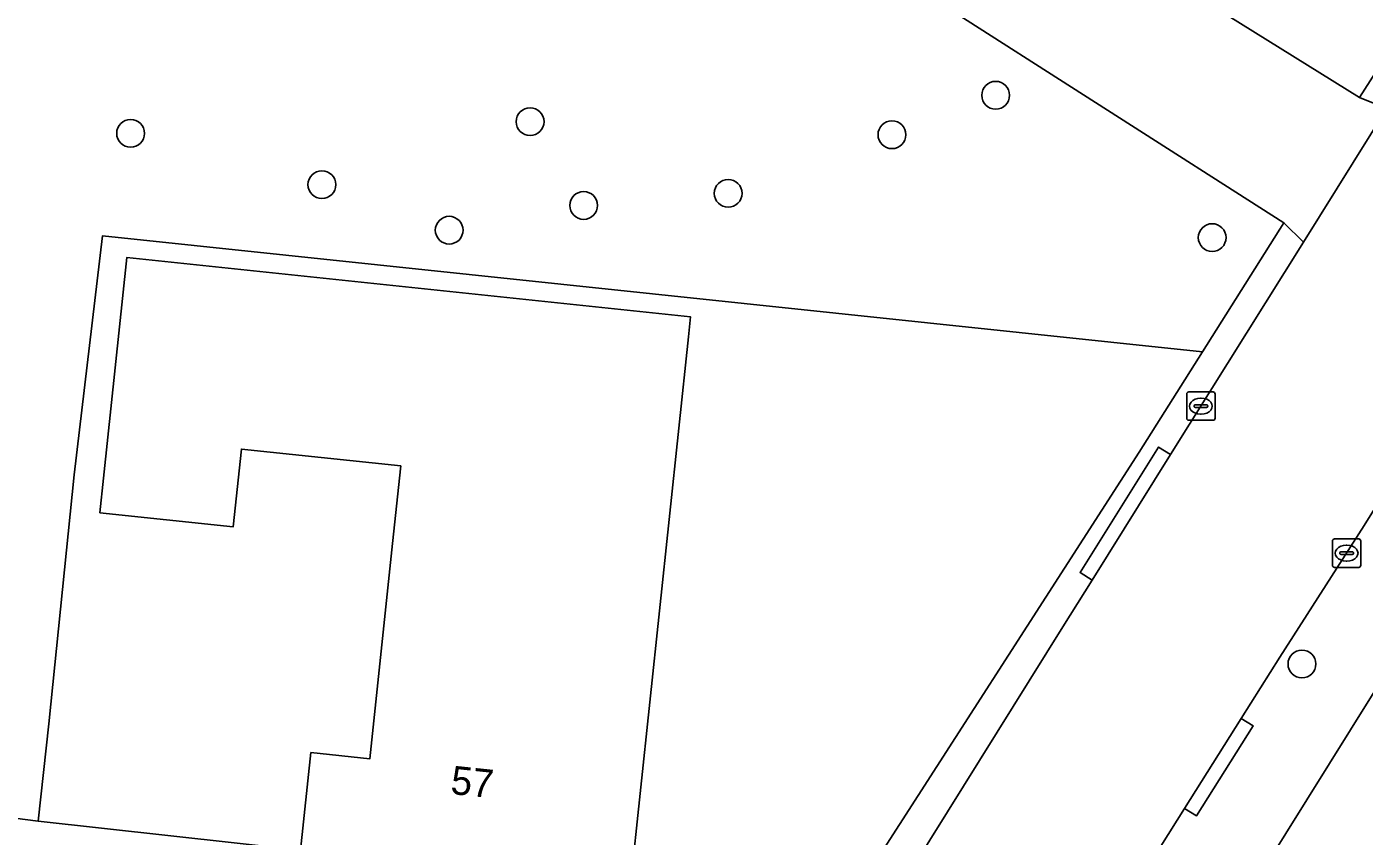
# Model space of a CAD drawing. Extents: x 162396 to 163643, y 386452 to 387406.
# Drawn here: x 162900.94 to 162948.05, y 387017.88 to 387046.39 of the extents above; entities that cross this region are included whole.
import ezdxf

# ---------------------------------------------------------------- set-up
doc = ezdxf.new("R2010")
doc.units = 0
for name, color, linetype in [('IMGEO_Boom', 7, 'Continuous'), ('IMGEO_Erf', 7, 'Continuous'), ('IMGEO_Groenvoorziening', 7, 'Continuous'), ('IMGEO_Kolk', 7, 'Continuous'), ('IMGEO_Pand', 7, 'Continuous'), ('IMGEO_Pand_nummerreeks', 7, 'Continuous'), ('IMGEO_Rijbaan_lokaal_open', 7, 'Continuous'), ('IMGEO_Voetpad_open', 7, 'Continuous')]:
    doc.layers.add(name, color=color, linetype=linetype)

msp = doc.modelspace()

# ---------------------------------------------------------------- linework, layer by layer
at = {"layer": 'IMGEO_Boom'}
for centre in [(162935.067, 387043.977), (162904.598, 387042.636), (162918.67, 387043.047), (162931.413, 387042.586), (162911.336, 387040.83), (162925.645, 387040.521), (162920.557, 387040.096), (162915.82, 387039.225), (162942.692, 387038.965), (162945.853, 387023.948)]:
    msp.add_circle(centre, 0.489, dxfattribs=at)
at = {"layer": 'IMGEO_Erf'}
msp.add_lwpolyline([(162940.119, 387031.406), (162942.349, 387034.94), (162903.611, 387039.027), (162902.613, 387030.613), (162901.724, 387021.841), (162901.346, 387018.415), (162910.588, 387017.396), (162910.951, 387020.828), (162913.025, 387020.609), (162913.826, 387028.186), (162914.115, 387030.921), (162908.504, 387031.514), (162908.215, 387028.779), (162903.517, 387029.275), (162903.646, 387030.495), (162904.467, 387038.268), (162924.323, 387036.171), (162924.249, 387035.467), (162922.211, 387016.169), (162929.704, 387015.236)], close=True, dxfattribs=at)
msp.add_lwpolyline([(162989.314, 387008.671), (162953.541, 387031.202), (162934.073, 387000), (162925.999, 386987.383), (162920.22, 386977.995), (162917.756, 386973.029), (162916.265, 386969.23), (162904.686, 386937.076)], dxfattribs=at)
at = {"layer": 'IMGEO_Groenvoorziening'}
msp.add_lwpolyline([(162964.245, 387069.484), (162941.168, 387071.891), (162939.105, 387055.217), (162936.596, 387055.509), (162935.833, 387055.438), (162935.116, 387055.166), (162934.413, 387053.638), (162934.581, 387052.537), (162935.398, 387051.666), (162947.885, 387043.899)], close=True, dxfattribs=at)
msp.add_lwpolyline([(162884.304, 387046.585), (162885.26, 387045.98), (162886.148, 387045.279), (162888.823, 387042.622), (162893.785, 387046.071), (162900.294, 387045.345), (162898.918, 387024.528), (162893.576, 387025.17), (162892.921, 387019.487), (162901.346, 387018.415), (162901.724, 387021.841), (162902.613, 387030.613), (162903.611, 387039.027), (162942.349, 387034.94), (162945.216, 387039.485), (162932.8, 387047.432)], dxfattribs=at)
at = {"layer": 'IMGEO_Kolk'}
for p, q in [((162941.794, 387032.603), (162941.794, 387033.455)), ((162941.869, 387033.529), (162942.721, 387033.529)), ((162942.282, 387033.309), (162942.307, 387033.309)), ((162942.795, 387033.455), (162942.795, 387032.603)), ((162942.053, 387033.023), (162942.053, 387033.035)), ((162942.491, 387032.986), (162942.093, 387032.986)), ((162942.096, 387033.072), (162942.494, 387033.072)), ((162942.305, 387032.749), (162942.28, 387032.749)), ((162942.537, 387033.035), (162942.537, 387033.023)), ((162942.721, 387032.529), (162941.869, 387032.529)), ((162946.926, 387027.425), (162946.926, 387028.277)), ((162947.001, 387028.351), (162947.853, 387028.351)), ((162947.414, 387028.131), (162947.439, 387028.131)), ((162947.927, 387028.277), (162947.927, 387027.425)), ((162947.185, 387027.845), (162947.185, 387027.857)), ((162947.623, 387027.808), (162947.225, 387027.808)), ((162947.228, 387027.894), (162947.626, 387027.894)), ((162947.437, 387027.571), (162947.412, 387027.571)), ((162947.669, 387027.857), (162947.669, 387027.845)), ((162947.853, 387027.351), (162947.001, 387027.351))]:
    msp.add_line(p, q, dxfattribs=at)
for points in [[(162941.794, 387032.603), (162941.794, 387033.455)], [(162941.869, 387033.529), (162942.721, 387033.529)], [(162942.795, 387033.455), (162942.795, 387032.603)], [(162942.721, 387032.529), (162941.869, 387032.529)], [(162946.926, 387027.425), (162946.926, 387028.277)], [(162947.001, 387028.351), (162947.853, 387028.351)], [(162947.927, 387028.277), (162947.927, 387027.425)], [(162947.853, 387027.351), (162947.001, 387027.351)]]:
    msp.add_lwpolyline(points, dxfattribs=at)
for centre, radius, start, end in [((162941.871, 387033.453), 0.0765, 91.552, 178.448), ((162941.871, 387033.453), 0.0765, 91.552, 178.448), ((162942.719, 387033.453), 0.0765, 1.552, 88.448), ((162942.719, 387033.453), 0.0765, 1.552, 88.448), ((162942.093, 387033.032), 0.0403, 85.8775, 175.7526), ((162942.09, 387033.022), 0.0366, 178.938, 274.7102), ((162942.494, 387033.029), 0.043, 264.8664, 352.4533), ((162942.498, 387033.034), 0.0386, 1.7309, 96.639), ((162941.871, 387032.605), 0.0765, 181.552, 268.448), ((162941.871, 387032.605), 0.0765, 181.552, 268.448), ((162942.719, 387032.605), 0.0765, 271.552, 358.448), ((162942.719, 387032.605), 0.0765, 271.552, 358.448), ((162947.003, 387028.275), 0.0765, 91.552, 178.448), ((162947.003, 387028.275), 0.0765, 91.552, 178.448), ((162947.851, 387028.275), 0.0765, 1.552, 88.448), ((162947.851, 387028.275), 0.0765, 1.552, 88.448), ((162947.225, 387027.854), 0.0403, 85.8775, 175.7526), ((162947.222, 387027.844), 0.0366, 178.938, 274.7102), ((162947.626, 387027.851), 0.043, 264.8664, 352.4533), ((162947.63, 387027.856), 0.0386, 1.7309, 96.639), ((162947.003, 387027.427), 0.0765, 181.552, 268.448), ((162947.003, 387027.427), 0.0765, 181.552, 268.448), ((162947.851, 387027.427), 0.0765, 271.552, 358.448), ((162947.851, 387027.427), 0.0765, 271.552, 358.448)]:
    msp.add_arc(centre, radius, start, end, dxfattribs=at)
for centre, major_axis, ratio, start_param, end_param in [((162942.281, 387033.029), (-0.387, 0.002), 0.722429, 4.712389, 7.853982), ((162942.306, 387033.029), (-0.39, 0.002), 0.717154, 1.570796, 4.712389), ((162947.413, 387027.851), (-0.387, 0.002), 0.722429, 4.712389, 7.853982), ((162947.438, 387027.851), (-0.39, 0.002), 0.717154, 1.570796, 4.712389)]:
    msp.add_ellipse(centre, major_axis=major_axis, ratio=ratio, start_param=start_param, end_param=end_param, dxfattribs=at)
at = {"layer": 'IMGEO_Pand'}
msp.add_lwpolyline([(162922.211, 387016.169), (162924.249, 387035.467), (162924.323, 387036.171), (162904.467, 387038.268), (162903.646, 387030.495), (162903.517, 387029.275), (162908.215, 387028.779), (162908.504, 387031.514), (162914.115, 387030.921), (162913.826, 387028.186), (162913.025, 387020.609), (162910.951, 387020.828), (162910.588, 387017.396)], close=True, dxfattribs=at)
at = {"layer": 'IMGEO_Rijbaan_lokaal_open'}
for points in [[(162947.885, 387043.899), (162935.398, 387051.666), (162934.581, 387052.537), (162934.413, 387053.638), (162936.765, 387072.408), (162927.001, 387073.553), (162927.634, 387072.835)], [(162966.768, 387071.483), (162948.849, 387043.507), (162945.907, 387038.803), (162941.229, 387031.323), (162938.465, 387026.904), (162937.436, 387025.258), (162921.686, 387000.002), (162915.342, 386989.987), (162914.431, 386990.593), (162914.143, 386990.14), (162911.404, 386985.942), (162911.138, 386985.441), (162912.089, 386984.831), (162909.331, 386979.699), (162906.632, 386973.865), (162905.275, 386970.114), (162896.686, 386945.321)], [(162928.216, 387071.142), (162925.71, 387048.745), (162929.833, 387048.448), (162929.843, 387048.447), (162930.466, 387048.352), (162931.078, 387048.201), (162931.674, 387047.997), (162932.25, 387047.739), (162932.8, 387047.432), (162945.216, 387039.485), (162945.907, 387038.803), (162948.849, 387043.507), (162947.885, 387043.899)], [(162893.927, 386924.59), (162901.627, 386939.333), (162906.38, 386952.275), (162909.185, 386960.036), (162912.927, 386970.387), (162914.676, 386974.714), (162915.597, 386976.559), (162916.277, 386977.92), (162917.178, 386979.724), (162920.646, 386985.26), (162923.023, 386989.056), (162927.543, 386996.272), (162929.878, 387000), (162929.936, 387000.092), (162941.722, 387018.853), (162943.715, 387022.032), (162945.076, 387024.193), (162948.049, 387028.821), (162949.072, 387030.463), (162949.283, 387030.941), (162957.556, 387044.115), (162957.708, 387044.272), (162960.889, 387049.333)]]:
    msp.add_lwpolyline(points, dxfattribs=at)
at = {"layer": 'IMGEO_Voetpad_open'}
for points in [[(162969.628, 387075.626), (162972.815, 387079.637), (162976.657, 387083.529), (162975.905, 387084.367), (162972.077, 387080.389), (162968.68, 387076.216), (162965.976, 387072.585), (162964.245, 387069.484), (162947.885, 387043.899), (162948.849, 387043.507), (162966.768, 387071.483)], [(162937.436, 387025.258), (162938.465, 387026.904), (162938.04, 387027.166), (162940.804, 387031.585), (162941.229, 387031.323), (162945.907, 387038.803), (162945.216, 387039.485), (162942.349, 387034.94), (162940.119, 387031.406), (162929.704, 387015.236), (162926.997, 387010.375), (162926.857, 387010.23), (162920.419, 387000), (162914.431, 386990.593), (162915.342, 386989.987), (162921.686, 387000.002)], [(162938.465, 387026.904), (162941.229, 387031.323), (162940.804, 387031.585), (162938.04, 387027.166)], [(162943.715, 387022.032), (162941.722, 387018.853), (162942.139, 387018.594), (162944.139, 387021.769)]]:
    msp.add_lwpolyline(points, close=True, dxfattribs=at)
for points in [[(162916.265, 386969.23), (162917.756, 386973.029), (162920.22, 386977.995), (162925.999, 386987.383), (162934.073, 387000), (162953.541, 387031.202), (162954.737, 387033.221)], [(162948.049, 387028.821), (162945.076, 387024.193), (162943.715, 387022.032), (162944.139, 387021.769), (162942.139, 387018.594), (162941.722, 387018.853), (162929.936, 387000.092), (162930.083, 387000), (162930.338, 386999.84), (162927.95, 386996.017), (162927.543, 386996.272), (162923.023, 386989.056)], [(162926.857, 387010.23), (162926.997, 387010.375), (162929.704, 387015.236), (162922.211, 387016.169), (162910.588, 387017.396), (162901.346, 387018.415), (162892.921, 387019.487), (162882.442, 387020.727), (162882.818, 387023.546)]]:
    msp.add_lwpolyline(points, dxfattribs=at)

# ---------------------------------------------------------------- texts
at = {"layer": 'IMGEO_Pand_nummerreeks'}
msp.add_text('57', height=1, rotation=353.9738, dxfattribs=at).set_placement((162915.843, 387019.375))

doc.saveas('drawing.dxf')
